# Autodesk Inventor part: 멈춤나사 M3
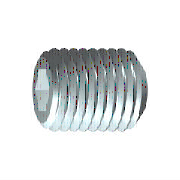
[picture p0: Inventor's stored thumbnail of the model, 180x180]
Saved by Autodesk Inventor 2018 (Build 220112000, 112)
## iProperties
IsCustomPart: 1
Created: 2012-02
Part Number: 멈춤나사 M3
Material: 강철, 연강
Description: 6각 소켓 머리 없는 멈춤 나사
Document SubType Name: Modeling
Standard: KS B 1028
Designer: mduedu
Standards Organization: KS
Language: ko-KR
Size Designation: 납작점M3x8
Categories: <MemberInstance><Categories><Category DisplayName="조임쇠" InternalName="e4da775c-781d-43d5-af7c-5136215cf5a6" Mnemonic="FSTN"><Category DisplayName="볼트" InternalN
Density: 1 g/cm^3
Appearance: 강철
Author: mduedu
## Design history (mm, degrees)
sketch "스케치1"
  geometry: L1 (0, 0)-(5.5, 0); L2 (8, 0.866)-(8, 1.5); L3 (8, 1.5)-(0, 1.5); L4 (8, 0.866)-(6, 0.866); L5 (6, 0.866)-(5.5, 0); L6 (0, -0.3)-(0, 1.8) reference; L7 (0, 1.5)-(0, 0)
  constraints: 13 end point, 3 parallel, 1 collinear, 1 perpendicular, 1 point on line
  dimensions: "d0" = 2 distance of L2.start L4.end (= INTI); "d1" = 60 deg angle of L5 L1; "d2" = 3 diameter of L3 L1 (= NND); "d3" = 1.73205 diameter of L4 L1 (= 1.1547 x SW); "d5" = 8 distance from line of L2 L3.end (= NLG)
revolve "본체" sketch "스케치1" stored, may be unused: angle "d6" = 90 deg
sketch "스케치2"
  geometry: L1 (-0.433, 0.75)-(0.433, 0.75); L2 (0.433, 0.75)-(0.866, 0); L3 (0.866, 0)-(0.433, -0.75); L4 (0.433, -0.75)-(-0.433, -0.75); L5 (-0.433, -0.75)-(-0.866, 0); L6 (-0.866, 0)-(-0.433, 0.75); A1 r 0.866 centre (0, 0) between (-0.433, 0.75) and (0.433, 0.75) reference; 2 further points
  constraints: 12 end point, 2 point on circle, 1 coincident, 1 horizontal, 11 other
extrude "슬롯" join sketch "스케치2" taper "d9" = 0 deg; stored distance "d21" = 10
workaxis "Work Axis1"
workplane "Work Plane1"
body "Solid1"
chamfer "모따기1" distance "d7" = 0.30673 (= -0.5 x GD1 + 0.5 x NND); stored, may be unused: angle "d8" = 45 deg (= FAWI), second distance "d29" = 0.30673 (= -0.5 x GD1 + 0.5 x NND)
feature "스레드" dims "d11" = 8 (= NLG), "d12" = 0
chamfer "모따기2" distance "d13" = 0.30673 (= -0.5 x GD1 + 0.5 x NND); stored, may be unused: angle "d14" = 45 deg (= FAWI), second distance "d30" = 0.30673 (= -0.5 x GD1 + 0.5 x NND)
other parameters: "NND" = 3 [user parameter; used in 5 equation terms], "NLG" = 8 [user parameter; used in 2 equation terms], "INTI" = 2 [user parameter; used in 1 equation term], "FAWI" = 45 deg [user parameter; used in 2 equation terms], "SW" = 1.5 [user parameter; used in 2 equation terms], "GD1" = 2.38655 (= THREADDIA - 1.2269 x PTC) [user parameter; used in 4 equation terms], "d4" = 0, "FAWI1" = 45 deg [user parameter], "d15" = 0, "d31" = 0, "GUL" = 0.30673 (= 0.61345 x PTC) [user parameter], "SPD" = 2 [user parameter], "TOA" = 30 deg [user parameter], "THREADDIA" = 3 [user parameter; used in 1 equation term], "PTC" = 0.5 [user parameter; used in 4 equation terms], "GAL" = 0.30673 (= 0.61345 x PTC) [user parameter], "E0" = 1.7325 (= 1.155 x SW) [user parameter]
